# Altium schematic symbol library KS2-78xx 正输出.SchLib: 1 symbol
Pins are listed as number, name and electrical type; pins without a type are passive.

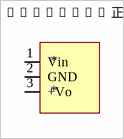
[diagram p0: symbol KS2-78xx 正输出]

## KS2-78xx 正输出
designator *
footprint Model Name (Footprint not found)
pins: 1 Vin, 2 GND, 3 +Vo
